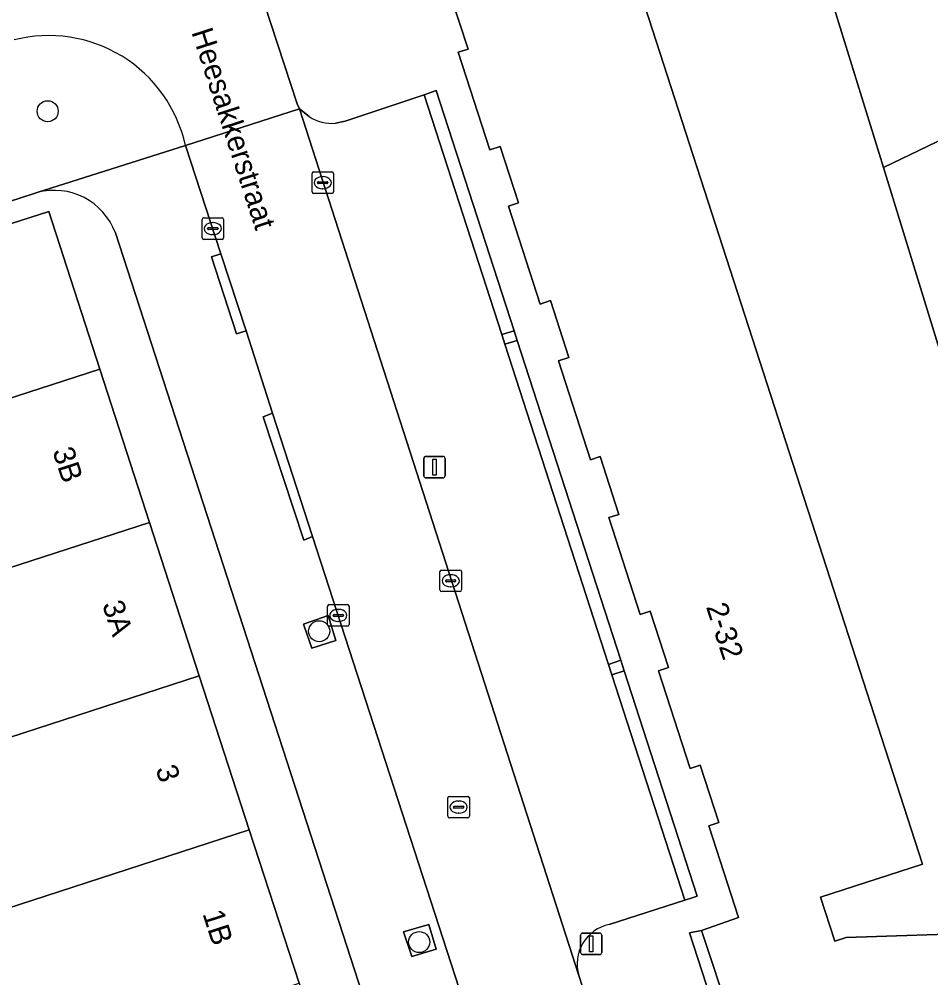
# Model space of a CAD drawing. Extents: x 159262 to 160143, y 383399 to 384319.
# Drawn here: x 159547.3 to 159589.68, y 383914.24 to 383958.79 of the extents above; entities that cross this region are included whole.
import ezdxf

# ---------------------------------------------------------------- set-up
doc = ezdxf.new("R2010")
doc.units = 0
for name, color, linetype in [('IMGEO_Boom', 7, 'Continuous'), ('IMGEO_Erf', 7, 'Continuous'), ('IMGEO_Groenvoorziening', 7, 'Continuous'), ('IMGEO_Haag', 7, 'Continuous'), ('IMGEO_Kolk', 7, 'Continuous'), ('IMGEO_Lichtmast', 7, 'Continuous'), ('IMGEO_Openbare_ruimte_label', 7, 'Continuous'), ('IMGEO_Pand', 7, 'Continuous'), ('IMGEO_Pand_nummerreeks', 7, 'Continuous'), ('IMGEO_Parkeervlak_open', 7, 'Continuous'), ('IMGEO_Rijbaan_lokaal_open', 7, 'Continuous'), ('IMGEO_Rioolput', 7, 'Continuous'), ('IMGEO_Voetpad_open', 7, 'Continuous')]:
    doc.layers.add(name, color=color, linetype=linetype)

msp = doc.modelspace()

# ---------------------------------------------------------------- linework, layer by layer
at = {"layer": 'IMGEO_Boom'}
for centre in [(159548.628, 383954.508), (159561.248, 383930.348), (159565.896, 383915.907)]:
    msp.add_circle(centre, 0.489, dxfattribs=at)
at = {"layer": 'IMGEO_Erf'}
for points in [[(159567.313, 383964.895), (159565.428, 383964.297), (159566.72, 383960.354), (159571.477, 383961.895), (159575.187, 383963.096), (159589.292, 383919.531), (159584.548, 383917.995), (159585.217, 383915.944), (159585.749, 383916.118), (159593.73, 383916.388), (159601.14, 383916.638), (159604.928, 383916.826), (159606.27, 383912.038), (159607.425, 383912.362), (159604.694, 383922.101), (159603.484, 383921.762), (159603.558, 383919.56), (159601.02, 383919.474), (159600.911, 383922.702), (159606.705, 383925.633), (159611.044, 383910.161), (159605.545, 383909.978)], [(159548.139, 383950.725), (159547.29, 383950.455), (159538.267, 383947.591), (159527.663, 383944.21), (159529.227, 383939.306), (159532.006, 383940.252), (159533.157, 383936.87), (159530.356, 383935.988), (159534.919, 383921.526), (159534.598, 383919.961), (159533.437, 383921.043), (159526.199, 383943.743), (159514.414, 383939.986), (159505.109, 383936.789)], [(159536.087, 383945.809), (159548.678, 383949.849), (159551.053, 383942.531), (159553.365, 383935.405), (159555.678, 383928.279), (159558, 383921.124), (159560.313, 383913.997), (159562.629, 383906.861), (159564.943, 383899.731), (159567.309, 383892.44), (159554.741, 383888.248), (159553.159, 383892.991), (159552.327, 383895.676), (159552.277, 383895.839), (159554.368, 383896.518), (159552.113, 383903.466), (159549.862, 383910.402), (159547.772, 383909.723), (159547.717, 383909.894), (159545.401, 383917.028)], [(159569.381, 383894.609), (159551.776, 383948.854)]]:
    msp.add_lwpolyline(points, dxfattribs=at)
msp.add_lwpolyline([(159603.571, 383932.676), (159594.771, 383928.286), (159590.01, 383943.692), (159587.477, 383951.891), (159585.059, 383959.717), (159591.087, 383962.582), (159594.048, 383955.054), (159597.174, 383947.107), (159597.393, 383946.549)], close=True, dxfattribs=at)
msp.add_arc((159548.937, 383947.805), 3.027, 20.2697, 105.2846, dxfattribs=at)
at = {"layer": 'IMGEO_Groenvoorziening'}
for points in [[(159566.685, 383955.473), (159566.126, 383955.272), (159569.734, 383944.13), (159570.306, 383944.3)], [(159570.45, 383943.857), (159569.88, 383943.678), (159574.695, 383928.808), (159575.264, 383929.003)], [(159562.026, 383929.912), (159561.667, 383931.074), (159560.514, 383930.68), (159560.553, 383930.578), (159560.907, 383929.557)], [(159575.424, 383928.511), (159574.853, 383928.319), (159578.244, 383917.849), (159578.584, 383917.959), (159578.819, 383918.035)], [(159566.69, 383915.572), (159566.34, 383916.724), (159565.171, 383916.383), (159565.552, 383915.234)]]:
    msp.add_lwpolyline(points, close=True, dxfattribs=at)
at = {"layer": 'IMGEO_Haag'}
for points in [[(159566.685, 383955.473), (159566.126, 383955.272), (159569.734, 383944.13), (159570.306, 383944.3)], [(159570.45, 383943.857), (159569.88, 383943.678), (159574.695, 383928.808), (159575.264, 383929.003)], [(159575.424, 383928.511), (159574.853, 383928.319), (159578.244, 383917.849), (159578.584, 383917.959), (159578.819, 383918.035)]]:
    msp.add_lwpolyline(points, close=True, dxfattribs=at)
at = {"layer": 'IMGEO_Kolk'}
for p, q in [((159560.916, 383950.762), (159560.916, 383951.614)), ((159560.991, 383951.688), (159561.843, 383951.688)), ((159561.917, 383951.614), (159561.917, 383950.762)), ((159561.175, 383951.182), (159561.175, 383951.194)), ((159561.613, 383951.145), (159561.215, 383951.145)), ((159561.218, 383951.231), (159561.616, 383951.231)), ((159561.404, 383951.468), (159561.429, 383951.468)), ((159561.659, 383951.194), (159561.659, 383951.182)), ((159561.843, 383950.688), (159560.991, 383950.688)), ((159561.427, 383950.908), (159561.402, 383950.908)), ((159555.805, 383948.63), (159555.805, 383949.482)), ((159555.88, 383949.556), (159556.732, 383949.556)), ((159556.293, 383949.336), (159556.318, 383949.336)), ((159556.806, 383949.482), (159556.806, 383948.63)), ((159556.064, 383949.05), (159556.064, 383949.062)), ((159556.502, 383949.013), (159556.104, 383949.013)), ((159556.107, 383949.099), (159556.505, 383949.099)), ((159556.548, 383949.062), (159556.548, 383949.05)), ((159556.732, 383948.556), (159555.88, 383948.556)), ((159556.316, 383948.776), (159556.291, 383948.776)), ((159566.863, 383932.265), (159566.863, 383933.117)), ((159566.938, 383933.191), (159567.79, 383933.191)), ((159567.351, 383932.971), (159567.376, 383932.971)), ((159567.864, 383933.117), (159567.864, 383932.265)), ((159567.122, 383932.685), (159567.122, 383932.697)), ((159567.56, 383932.648), (159567.162, 383932.648)), ((159567.165, 383932.734), (159567.563, 383932.734)), ((159567.374, 383932.411), (159567.349, 383932.411)), ((159567.606, 383932.697), (159567.606, 383932.685)), ((159567.79, 383932.191), (159566.938, 383932.191)), ((159561.637, 383930.657), (159561.637, 383931.509)), ((159561.712, 383931.583), (159562.564, 383931.583)), ((159562.638, 383931.509), (159562.638, 383930.657)), ((159561.896, 383931.077), (159561.896, 383931.089)), ((159562.334, 383931.04), (159561.936, 383931.04)), ((159561.939, 383931.126), (159562.337, 383931.126)), ((159562.125, 383931.363), (159562.15, 383931.363)), ((159562.38, 383931.089), (159562.38, 383931.077)), ((159562.564, 383930.583), (159561.712, 383930.583)), ((159562.148, 383930.803), (159562.123, 383930.803))]:
    msp.add_line(p, q, dxfattribs=at)
for points in [[(159560.916, 383950.762), (159560.916, 383951.614)], [(159560.991, 383951.688), (159561.843, 383951.688)], [(159561.917, 383951.614), (159561.917, 383950.762)], [(159561.843, 383950.688), (159560.991, 383950.688)], [(159555.805, 383948.63), (159555.805, 383949.482)], [(159555.88, 383949.556), (159556.732, 383949.556)], [(159556.806, 383949.482), (159556.806, 383948.63)], [(159556.732, 383948.556), (159555.88, 383948.556)], [(159566.863, 383932.265), (159566.863, 383933.117)], [(159566.938, 383933.191), (159567.79, 383933.191)], [(159567.864, 383933.117), (159567.864, 383932.265)], [(159567.79, 383932.191), (159566.938, 383932.191)], [(159561.637, 383930.657), (159561.637, 383931.509)], [(159561.712, 383931.583), (159562.564, 383931.583)], [(159562.638, 383931.509), (159562.638, 383930.657)], [(159562.564, 383930.583), (159561.712, 383930.583)]]:
    msp.add_lwpolyline(points, dxfattribs=at)
for centre, radius, start, end in [((159560.993, 383951.612), 0.0765, 91.552, 178.448), ((159560.993, 383951.612), 0.0765, 91.552, 178.448), ((159561.841, 383951.612), 0.0765, 1.552, 88.448), ((159561.841, 383951.612), 0.0765, 1.552, 88.448), ((159561.215, 383951.191), 0.0403, 85.8775, 175.7526), ((159561.212, 383951.181), 0.0366, 178.938, 274.7102), ((159561.616, 383951.188), 0.043, 264.8664, 352.4533), ((159561.62, 383951.193), 0.0386, 1.7309, 96.639), ((159560.993, 383950.764), 0.0765, 181.552, 268.448), ((159560.993, 383950.764), 0.0765, 181.552, 268.448), ((159561.841, 383950.764), 0.0765, 271.552, 358.448), ((159561.841, 383950.764), 0.0765, 271.552, 358.448), ((159555.882, 383949.48), 0.0765, 91.552, 178.448), ((159555.882, 383949.48), 0.0765, 91.552, 178.448), ((159556.73, 383949.48), 0.0765, 1.552, 88.448), ((159556.73, 383949.48), 0.0765, 1.552, 88.448), ((159556.104, 383949.059), 0.0403, 85.8775, 175.7526), ((159556.101, 383949.049), 0.0366, 178.938, 274.7102), ((159556.505, 383949.056), 0.043, 264.8664, 352.4533), ((159556.509, 383949.061), 0.0386, 1.7309, 96.639), ((159555.882, 383948.632), 0.0765, 181.552, 268.448), ((159555.882, 383948.632), 0.0765, 181.552, 268.448), ((159556.73, 383948.632), 0.0765, 271.552, 358.448), ((159556.73, 383948.632), 0.0765, 271.552, 358.448), ((159566.94, 383933.115), 0.0765, 91.552, 178.448), ((159566.94, 383933.115), 0.0765, 91.552, 178.448), ((159567.788, 383933.115), 0.0765, 1.552, 88.448), ((159567.788, 383933.115), 0.0765, 1.552, 88.448), ((159567.162, 383932.694), 0.0403, 85.8775, 175.7526), ((159567.159, 383932.684), 0.0366, 178.938, 274.7102), ((159567.563, 383932.691), 0.043, 264.8664, 352.4533), ((159567.567, 383932.696), 0.0386, 1.7309, 96.639), ((159566.94, 383932.267), 0.0765, 181.552, 268.448), ((159566.94, 383932.267), 0.0765, 181.552, 268.448), ((159567.788, 383932.267), 0.0765, 271.552, 358.448), ((159567.788, 383932.267), 0.0765, 271.552, 358.448), ((159561.714, 383931.507), 0.0765, 91.552, 178.448), ((159561.714, 383931.507), 0.0765, 91.552, 178.448), ((159562.562, 383931.507), 0.0765, 1.552, 88.448), ((159562.562, 383931.507), 0.0765, 1.552, 88.448), ((159561.936, 383931.086), 0.0403, 85.8775, 175.7526), ((159561.933, 383931.076), 0.0366, 178.938, 274.7102), ((159562.337, 383931.083), 0.043, 264.8664, 352.4533), ((159562.341, 383931.088), 0.0386, 1.7309, 96.639), ((159561.714, 383930.659), 0.0765, 181.552, 268.448), ((159561.714, 383930.659), 0.0765, 181.552, 268.448), ((159562.562, 383930.659), 0.0765, 271.552, 358.448), ((159562.562, 383930.659), 0.0765, 271.552, 358.448)]:
    msp.add_arc(centre, radius, start, end, dxfattribs=at)
for centre, major_axis, ratio, start_param, end_param in [((159561.403, 383951.188), (-0.387, 0.002), 0.722429, 4.712389, 7.853982), ((159561.428, 383951.188), (-0.39, 0.002), 0.717154, 1.570796, 4.712389), ((159556.292, 383949.056), (-0.387, 0.002), 0.722429, 4.712389, 7.853982), ((159556.317, 383949.056), (-0.39, 0.002), 0.717154, 1.570796, 4.712389), ((159567.35, 383932.691), (-0.387, 0.002), 0.722429, 4.712389, 7.853982), ((159567.375, 383932.691), (-0.39, 0.002), 0.717154, 1.570796, 4.712389), ((159562.124, 383931.083), (-0.387, 0.002), 0.722429, 4.712389, 7.853982), ((159562.149, 383931.083), (-0.39, 0.002), 0.717154, 1.570796, 4.712389)]:
    msp.add_ellipse(centre, major_axis=major_axis, ratio=ratio, start_param=start_param, end_param=end_param, dxfattribs=at)
at = {"layer": 'IMGEO_Lichtmast'}
for p, q in [((159566.11, 383937.573), (159566.11, 383938.373)), ((159566.11, 383938.373), (159566.11, 383937.573)), ((159566.21, 383938.473), (159567, 383938.473)), ((159567, 383938.473), (159566.21, 383938.473)), ((159567.1, 383938.373), (159567.1, 383937.573)), ((159567.1, 383937.573), (159567.1, 383938.373)), ((159567, 383937.473), (159566.21, 383937.473)), ((159566.21, 383937.473), (159567, 383937.473)), ((159573.497, 383916.325), (159574.287, 383916.325)), ((159574.287, 383916.325), (159573.497, 383916.325)), ((159573.397, 383915.425), (159573.397, 383916.225)), ((159573.397, 383916.225), (159573.397, 383915.425)), ((159574.387, 383916.225), (159574.387, 383915.425)), ((159574.387, 383915.425), (159574.387, 383916.225)), ((159574.287, 383915.325), (159573.497, 383915.325)), ((159573.497, 383915.325), (159574.287, 383915.325))]:
    msp.add_line(p, q, dxfattribs=at)
for points in [[(159566.53, 383938.348), (159566.68, 383938.348), (159566.68, 383937.598), (159566.53, 383937.598), (159566.53, 383938.348)], [(159573.817, 383916.2), (159573.967, 383916.2), (159573.967, 383915.45), (159573.817, 383915.45), (159573.817, 383916.2)]]:
    msp.add_lwpolyline(points, dxfattribs=at)
for centre, start, end in [((159566.21, 383938.373), 90, 180), ((159566.21, 383938.373), 90, 180), ((159567, 383938.373), 0, 90), ((159567, 383938.373), 360, 90), ((159566.21, 383937.573), 180, 270), ((159566.21, 383937.573), 180, 270), ((159567, 383937.573), 270, 0), ((159567, 383937.573), 270, 0), ((159573.497, 383916.225), 90, 180), ((159573.497, 383916.225), 90, 180), ((159574.287, 383916.225), 0, 90), ((159574.287, 383916.225), 360, 90), ((159573.497, 383915.425), 180, 270), ((159573.497, 383915.425), 180, 270), ((159574.287, 383915.425), 270, 0), ((159574.287, 383915.425), 270, 0)]:
    msp.add_arc(centre, 0.1, start, end, dxfattribs=at)
at = {"layer": 'IMGEO_Pand'}
for points in [[(159593.73, 383916.388), (159585.749, 383916.118), (159585.217, 383915.944), (159584.548, 383917.995), (159589.292, 383919.531), (159575.187, 383963.096)], [(159567.329, 383959.997), (159568.171, 383957.394), (159567.713, 383957.245), (159569.181, 383952.712), (159569.662, 383952.867), (159570.51, 383950.246), (159570.042, 383950.095), (159571.514, 383945.55), (159572.003, 383945.708), (159572.856, 383943.072), (159572.369, 383942.914), (159573.858, 383938.314), (159574.311, 383938.46), (159575.18, 383935.778), (159574.706, 383935.625), (159576.163, 383931.126), (159576.635, 383931.279), (159577.484, 383928.656), (159577.023, 383928.506), (159578.49, 383923.975), (159578.964, 383924.128), (159579.83, 383921.454), (159579.356, 383921.3), (159580.741, 383917.04), (159579.023, 383916.44), (159580.365, 383912.385)]]:
    msp.add_lwpolyline(points, dxfattribs=at)
for points in [[(159587.477, 383951.891), (159594.048, 383955.054), (159591.087, 383962.582), (159585.059, 383959.717)], [(159597.174, 383947.107), (159594.048, 383955.054), (159587.477, 383951.891), (159590.01, 383943.692)], [(159540.524, 383939.113), (159551.053, 383942.531), (159548.678, 383949.849), (159536.087, 383945.809), (159537.615, 383941.048), (159537.727, 383940.675), (159539.798, 383941.348)], [(159540.762, 383931.324), (159553.365, 383935.405), (159551.053, 383942.531), (159540.524, 383939.113), (159542.781, 383932.158), (159540.709, 383931.486)], [(159540.762, 383931.324), (159543.08, 383924.181), (159555.678, 383928.279), (159553.365, 383935.405)], [(159558, 383921.124), (159555.678, 383928.279), (159543.08, 383924.181), (159545.401, 383917.028)], [(159547.717, 383909.894), (159560.313, 383913.997), (159558, 383921.124), (159545.401, 383917.028)]]:
    msp.add_lwpolyline(points, close=True, dxfattribs=at)
at = {"layer": 'IMGEO_Parkeervlak_open'}
for points in [[(159569.88, 383943.678), (159569.734, 383944.13), (159566.126, 383955.272), (159562.456, 383954.054), (159562.006, 383953.951)], [(159560.784, 383954.259), (159560.334, 383954.623), (159573.312, 383914.357)], [(159574.725, 383916.727), (159578.244, 383917.849), (159574.853, 383928.319), (159574.695, 383928.808), (159569.88, 383943.678)]]:
    msp.add_lwpolyline(points, dxfattribs=at)
for centre, radius, start, end in [((159561.83, 383955.832), 1.889, 236.3715, 275.3354), ((159575.129, 383914.88), 1.891, 102.3445, 196.0485)]:
    msp.add_arc(centre, radius, start, end, dxfattribs=at)
at = {"layer": 'IMGEO_Rijbaan_lokaal_open'}
msp.add_lwpolyline([(159555.033, 383952.923), (159560.334, 383954.623), (159560.232, 383954.847), (159557.786, 383962.289), (159555.239, 383970.036), (159554.304, 383972.881), (159549.095, 383971.183), (159549.823, 383968.867)], dxfattribs=at)
msp.add_lwpolyline([(159572.705, 383898.533), (159574.089, 383894.293), (159579.2, 383895.932), (159578.987, 383896.617), (159574.378, 383911.079), (159573.312, 383914.357), (159560.334, 383954.623), (159555.033, 383952.923), (159556.681, 383947.875), (159557.849, 383944.305), (159559.079, 383940.474), (159560.937, 383934.748), (159568.333, 383911.982), (159570.194, 383906.241), (159571.525, 383902.126)], close=True, dxfattribs=at)
msp.add_arc((159548.68, 383951.515), 6.507, 12.4928, 104.3756, dxfattribs=at)
at = {"layer": 'IMGEO_Rioolput'}
for p, q in [((159567.228, 383921.75), (159567.228, 383922.602)), ((159567.303, 383922.676), (159568.155, 383922.676)), ((159568.229, 383922.602), (159568.229, 383921.75)), ((159567.487, 383922.17), (159567.487, 383922.182)), ((159567.925, 383922.133), (159567.527, 383922.133)), ((159567.53, 383922.219), (159567.928, 383922.219)), ((159567.716, 383922.456), (159567.741, 383922.456)), ((159567.971, 383922.182), (159567.971, 383922.17)), ((159568.155, 383921.676), (159567.303, 383921.676)), ((159567.739, 383921.896), (159567.714, 383921.896))]:
    msp.add_line(p, q, dxfattribs=at)
for points in [[(159567.228, 383921.75), (159567.228, 383922.602)], [(159567.303, 383922.676), (159568.155, 383922.676)], [(159568.229, 383922.602), (159568.229, 383921.75)], [(159568.155, 383921.676), (159567.303, 383921.676)]]:
    msp.add_lwpolyline(points, dxfattribs=at)
for centre, radius, start, end in [((159567.305, 383922.6), 0.0765, 91.552, 178.448), ((159567.305, 383922.6), 0.0765, 91.552, 178.448), ((159568.153, 383922.6), 0.0765, 1.552, 88.448), ((159568.153, 383922.6), 0.0765, 1.552, 88.448), ((159567.527, 383922.179), 0.0403, 85.8775, 175.7526), ((159567.524, 383922.169), 0.0366, 178.938, 274.7102), ((159567.928, 383922.176), 0.043, 264.8664, 352.4533), ((159567.932, 383922.181), 0.0386, 1.7309, 96.639), ((159567.305, 383921.752), 0.0765, 181.552, 268.448), ((159567.305, 383921.752), 0.0765, 181.552, 268.448), ((159568.153, 383921.752), 0.0765, 271.552, 358.448), ((159568.153, 383921.752), 0.0765, 271.552, 358.448)]:
    msp.add_arc(centre, radius, start, end, dxfattribs=at)
for centre, major_axis, ratio, start_param, end_param in [((159567.715, 383922.176), (-0.387, 0.002), 0.722429, 4.712389, 7.853982), ((159567.74, 383922.176), (-0.39, 0.002), 0.717154, 1.570796, 4.712389)]:
    msp.add_ellipse(centre, major_axis=major_axis, ratio=ratio, start_param=start_param, end_param=end_param, dxfattribs=at)
at = {"layer": 'IMGEO_Voetpad_open'}
for points in [[(159552.301, 383979.089), (159553.76, 383974.614), (159554.14, 383973.413), (159554.229, 383973.183), (159554.304, 383972.881), (159555.239, 383970.036), (159557.786, 383962.289), (159560.232, 383954.847), (159560.334, 383954.623), (159560.784, 383954.259)], [(159579.83, 383912.138), (159578.464, 383916.328), (159579.023, 383916.44), (159580.741, 383917.04), (159579.356, 383921.3), (159579.83, 383921.454), (159578.964, 383924.128), (159578.49, 383923.975), (159577.023, 383928.506), (159577.484, 383928.656), (159576.635, 383931.279), (159576.163, 383931.126), (159574.706, 383935.625), (159575.18, 383935.778), (159574.311, 383938.46), (159573.858, 383938.314), (159572.369, 383942.914), (159572.856, 383943.072), (159572.003, 383945.708), (159571.514, 383945.55), (159570.042, 383950.095), (159570.51, 383950.246), (159569.662, 383952.867), (159569.181, 383952.712), (159567.713, 383957.245), (159568.171, 383957.394), (159567.329, 383959.997)], [(159562.006, 383953.951), (159562.456, 383954.054), (159566.126, 383955.272), (159566.685, 383955.473), (159570.306, 383944.3), (159570.45, 383943.857), (159575.264, 383929.003), (159575.424, 383928.511), (159578.819, 383918.035), (159578.584, 383917.959), (159578.244, 383917.849), (159574.725, 383916.727)], [(159505.109, 383936.789), (159514.414, 383939.986), (159526.199, 383943.743), (159527.663, 383944.21), (159538.267, 383947.591), (159547.29, 383950.455), (159548.139, 383950.725), (159555.033, 383952.923)], [(159560.937, 383934.748), (159560.539, 383934.583), (159558.652, 383940.312), (159559.079, 383940.474), (159557.849, 383944.305), (159557.403, 383944.167), (159556.249, 383947.745), (159556.681, 383947.875), (159555.033, 383952.923), (159548.139, 383950.725)], [(159551.776, 383948.854), (159569.381, 383894.609)], [(159568.936, 383892.591), (159570.586, 383893.133), (159574.089, 383894.293), (159572.705, 383898.533), (159572.265, 383898.438), (159571.096, 383901.978), (159571.525, 383902.126), (159570.194, 383906.241), (159569.78, 383906.108), (159567.907, 383911.836), (159568.333, 383911.982), (159560.937, 383934.748)], [(159573.312, 383914.357), (159574.378, 383911.079)]]:
    msp.add_lwpolyline(points, dxfattribs=at)
for points in [[(159556.681, 383947.875), (159556.249, 383947.745), (159557.403, 383944.167), (159557.849, 383944.305)], [(159570.306, 383944.3), (159569.734, 383944.13), (159569.88, 383943.678), (159570.45, 383943.857)], [(159560.937, 383934.748), (159559.079, 383940.474), (159558.652, 383940.312), (159560.539, 383934.583)], [(159560.907, 383929.557), (159560.553, 383930.578), (159560.514, 383930.68), (159561.667, 383931.074), (159562.026, 383929.912)], [(159575.264, 383929.003), (159574.695, 383928.808), (159574.853, 383928.319), (159575.424, 383928.511)], [(159566.34, 383916.724), (159566.69, 383915.572), (159565.552, 383915.234), (159565.171, 383916.383)], [(159580.365, 383912.385), (159579.023, 383916.44), (159578.464, 383916.328), (159579.83, 383912.138)]]:
    msp.add_lwpolyline(points, close=True, dxfattribs=at)
for centre, radius, start, end in [((159548.68, 383951.515), 6.507, 12.4928, 104.3756), ((159561.83, 383955.832), 1.889, 236.3715, 275.3354), ((159548.937, 383947.805), 3.027, 20.2697, 105.2846), ((159575.129, 383914.88), 1.891, 102.3445, 196.0485)]:
    msp.add_arc(centre, radius, start, end, dxfattribs=at)

# ---------------------------------------------------------------- texts
at = {"layer": 'IMGEO_Openbare_ruimte_label'}
msp.add_text('Heesakkerstraat', height=1, rotation=287.9456, dxfattribs=at).set_placement((159555.302, 383958.187))
at = {"layer": 'IMGEO_Pand_nummerreeks'}
for s, rotation, p in [('3B', 287.9798, (159548.841, 383938.721)), ('3A', 287.9798, (159551.153, 383931.595)), ('2-32', 287.985, (159579.222, 383931.487)), ('3', 287.9798, (159553.634, 383923.952)), ('1B', 287.9798, (159555.816, 383917.227))]:
    msp.add_text(s, height=1, rotation=rotation, dxfattribs=at).set_placement(p)

doc.saveas('drawing.dxf')
